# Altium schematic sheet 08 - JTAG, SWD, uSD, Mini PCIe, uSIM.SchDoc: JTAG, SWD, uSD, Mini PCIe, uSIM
size A3; PageSetup: Record=PageOptions¦CenterHorizontal=True¦CenterVertical=True¦PrintScale=0.70¦XCorrection=1.00¦YCorrection=1.00¦PrintKind=0¦BorderSize=5000000¦LeftOffset=0¦BottomOffset=0¦Orientation=2¦PaperLength=4200¦PaperWidth=2970¦Scale=100¦PaperSource=7¦PrintQuality=600¦MediaType=1¦DitherType=10¦PaperKind=A4¦PrintScaleMode=1; Author: Juan Anzola; SheetNumber: 8; SheetTotal: 20
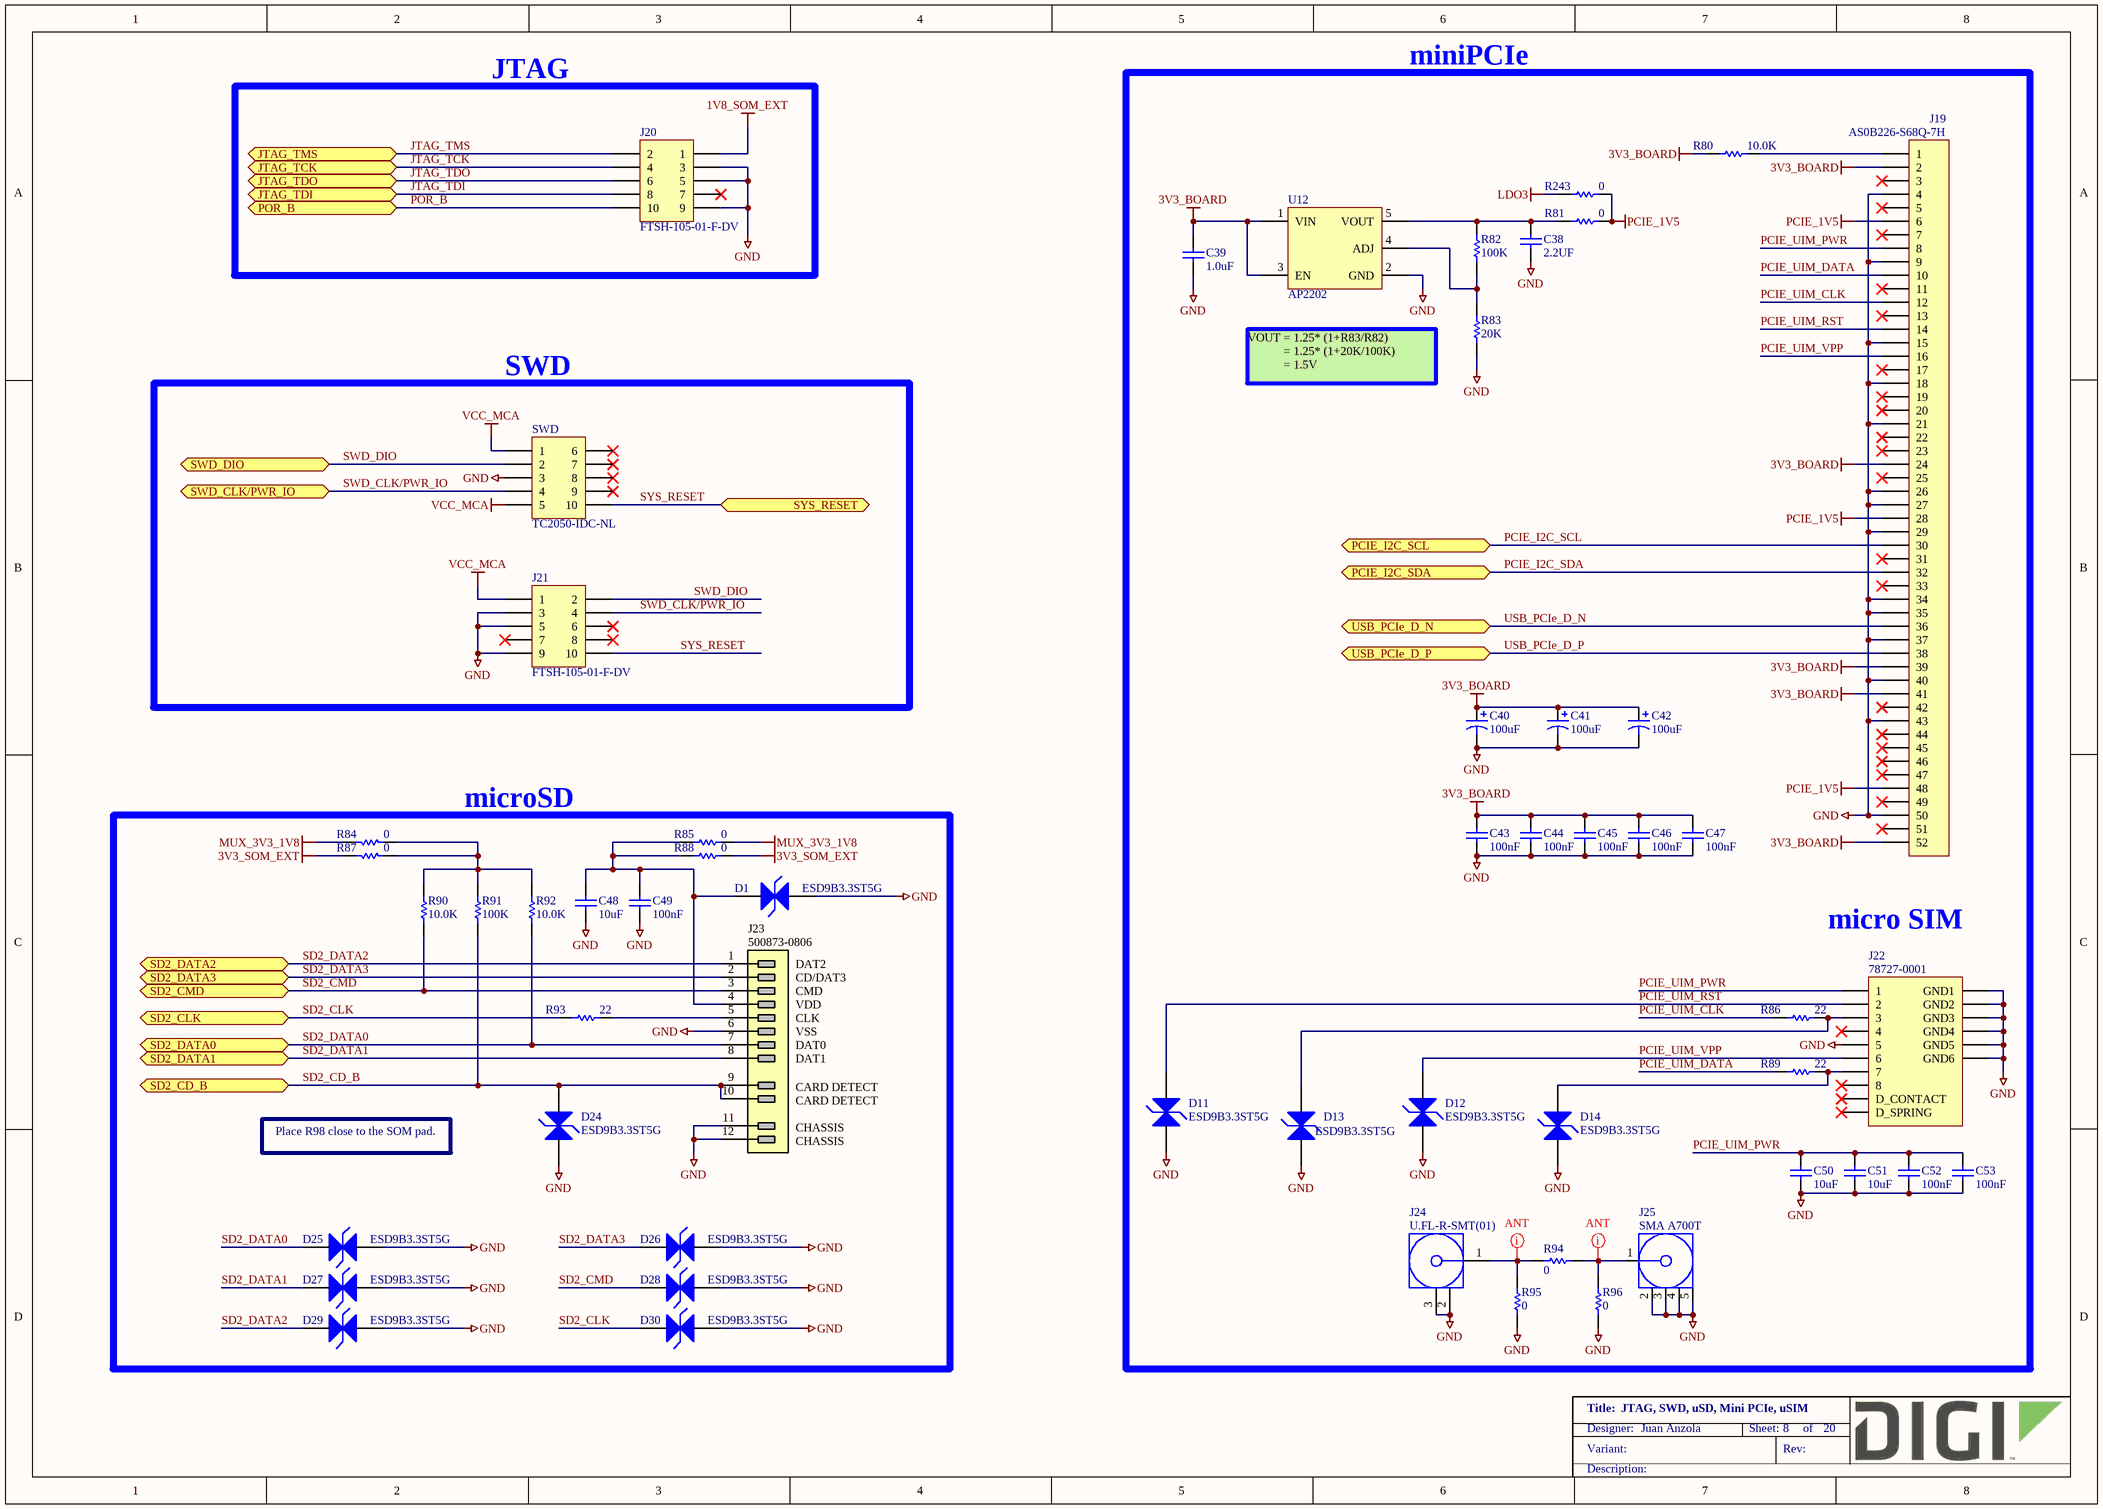
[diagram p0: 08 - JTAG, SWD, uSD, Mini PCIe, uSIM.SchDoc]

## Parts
C38  2.2UF  [CAPC1608X90N]
C39  1.0uF  [CAPC1005X55N]
C40  100uF  [CAPMP3216X120N]
C41  100uF  [CAPMP3216X120N]
C42  100uF  [CAPMP3216X120N]
C43  100nF  [CAPC1005X55N]
C44  100nF  [CAPC1005X55N]
C45  100nF  [CAPC1005X55N]
C46  100nF  [CAPC1005X55N]
C47  100nF  [CAPC1005X55N]
C48  10uF  [CAPC1005X55N]
C49  100nF  [CAPC1005X55N]
C50  10uF  [CAPC2013X135N]
C51  10uF  [CAPC2013X135N]
C52  100nF  [CAPC1005X55N]
C53  100nF  [CAPC1005X55N]
D1  ESD9B3.3ST5G  [SODFL1006X43AN12]
D11  ESD9B3.3ST5G  [SODFL1006X43AN12]
D12  ESD9B3.3ST5G  [SODFL1006X43AN12]
D13  ESD9B3.3ST5G  [SODFL1006X43AN12]
D14  ESD9B3.3ST5G  [SODFL1006X43AN12]
D24  ESD9B3.3ST5G  [SODFL1006X43AN12]
D25  ESD9B3.3ST5G  [SODFL1006X43AN12]
D26  ESD9B3.3ST5G  [SODFL1006X43AN12]
D27  ESD9B3.3ST5G  [SODFL1006X43AN12]
D28  ESD9B3.3ST5G  [SODFL1006X43AN12]
D29  ESD9B3.3ST5G  [SODFL1006X43AN12]
D30  ESD9B3.3ST5G  [SODFL1006X43AN12]
J19  Manufacturer_Part_Number: AS0B226-S68Q-7H  [FOXCONN_AS0B221-S68Q-7H]  (hidden comment: PCIe Minicard)
J20  FTSH-105-01-F-DV  [SAMTEC_FTSH-105-01-F-DV]
J21  FTSH-105-01-F-DV  [SAMTEC_FTSH-105-01-F-DV]
J22  78727-0001  [MOLEX_78727-0001]
J23  500873-0806  [MOLEX_500873-0806]
J24  U.FL-R-SMT(01)  [HIROSE_U.FL-R-SMT(01)]
J25  SMA A700T  [BOBBINTRON_SMA A700T]
R80  10.0K  [RESC1005X40N]
R81  0  [RESC1005X40N]
R82  100K  [RESC1005X40N]
R83  20K  [RESC1609X55N]
R84  0  [RESC1005X40N]
R85  0  [RESC1005X40N]
R86  22  [RESC1005X40N]
R87  0  [RESC1005X40N]
R88  0  [RESC1005X40N]
R89  22  [RESC1005X40N]
R90  10.0K  [RESC1005X40N]
R91  100K  [RESC1005X40N]
R92  10.0K  [RESC1005X40N]
R93  22  [RESC1005X40N]
R94  0  [RESC1005X40N]
R95  0  [RESC1005X40N]
R96  0  [RESC1005X40N]
R243  0  [RESC1005X40N]
SWD  TC2050-IDC-NL  [TC_TC2050-IDC-NL]  (no BOM)
U12  AP2202  [SOT95P280X145-5N]

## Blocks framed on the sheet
JTAG: J20
SWD: J21 SWD
microSD: C48 C49 D1 D24-D30 J23 R84 R85 R87 R88 R90-R93

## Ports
JTAG_TCK (bidir), JTAG_TDI (bidir), JTAG_TDO (bidir), JTAG_TMS (bidir), PCIE_I2C_SCL (bidir), PCIE_I2C_SDA (bidir), POR_B (bidir), SD2_CD_B (bidir), SD2_CLK (bidir), SD2_CMD (bidir), SD2_DATA0 (bidir), SD2_DATA1 (bidir), SD2_DATA2 (bidir), SD2_DATA3 (bidir), SWD_CLK/PWR_IO (bidir), SWD_DIO (bidir), SYS_RESET (bidir), USB_PCIe_D_N (bidir), USB_PCIe_D_P (bidir)

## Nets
1V8_SOM_EXT: J20.1
3V3_BOARD: C39.1 C40.1 C41.1 C42.1 C43.2 C44.2 C45.2 C46.2 C47.2 J19.2 J19.24 J19.39 J19.41 J19.52 R80.2 U12.1(VIN) U12.3(EN)
3V3_SOM_EXT: R87.2 R88.2
GND: C38.1 C39.2 C40.2 C41.2 C42.2 C43.1 C44.1 C45.1 C46.1 C47.1 C48.1 C49.1 C50.1 C51.1 C52.1 C53.1 D1.2 D11.1 D12.1 D13.1 D14.1 D24.2 D25.2 D26.2 D27.2 D28.2 D29.2 D30.2 J19.4 J19.9 J19.15 J19.18 J19.21 J19.26 J19.27 J19.29 J19.34 J19.35 J19.37 J19.40 J19.43 J19.50 J20.3 J20.5 J20.9 J21.3 J21.5 J21.9 J22.5 J22.11(GND1) J22.12(GND2) J22.13(GND3) J22.14(GND4) J22.15(GND5) J22.16(GND6) J23.6 J23.11 J23.12 J24.2(GND) J24.3(GND) J25.2(GND) J25.3(GND) J25.4(GND) J25.5(GND) R83.1 R95.1 R96.1 SWD.3 U12.2(GND)
LDO3: R243.1
MUX_3V3_1V8: R84.2 R85.2
PCIE_1V5: J19.6 J19.28 J19.48 R81.2 R243.2
VCC_MCA: J21.1 SWD.1 SWD.5
JTAG_TCK: J20.4 ; port JTAG_TCK
JTAG_TDI: J20.8 ; port JTAG_TDI
JTAG_TDO: J20.6 ; port JTAG_TDO
JTAG_TMS: J20.2 ; port JTAG_TMS
PCIE_I2C_SCL: J19.30 ; port PCIE_I2C_SCL
PCIE_I2C_SDA: J19.32 ; port PCIE_I2C_SDA
PCIE_UIM_CLK: J19.12 R86.1
PCIE_UIM_DATA: J19.10 R89.1
PCIE_UIM_PWR: C50.2 C51.2 C52.2 C53.2 J19.8 J22.1
PCIE_UIM_RST: D11.2 J19.14 J22.2
PCIE_UIM_VPP: D12.2 J19.16 J22.6
POR_B: J20.10 ; port POR_B
SD2_CD_B: D24.1 J23.9 J23.10 R91.2 ; port SD2_CD_B
SD2_CLK: D30.1 R93.1 ; port SD2_CLK
SD2_CMD: D28.1 J23.3 R90.1 ; port SD2_CMD
SD2_DATA0: D25.1 J23.7 R92.1 ; port SD2_DATA0
SD2_DATA1: D27.1 J23.8 ; port SD2_DATA1
SD2_DATA2: D29.1 J23.1 ; port SD2_DATA2
SD2_DATA3: D26.1 J23.2 ; port SD2_DATA3
SWD_CLK/PWR_IO: J21.4 SWD.4 ; port SWD_CLK/PWR_IO
SWD_DIO: J21.2 SWD.2 ; port SWD_DIO
SYS_RESET: J21.10 SWD.10 ; port SYS_RESET
USB_PCIe_D_N: J19.36 ; port USB_PCIe_D_N
USB_PCIe_D_P: J19.38 ; port USB_PCIe_D_P
NetC38_2: C38.2 R81.1 R82.2 U12.5(VOUT)
NetC48_2: C48.2 C49.2 D1.1 J23.4 R85.1 R88.1
NetD13_2: D13.2 J22.3 R86.2
NetD14_2: D14.2 J22.7 R89.2
NetJ19_1: J19.1 R80.1
NetJ23_5: J23.5 R93.2
NetJ24_1: J24.1(Signal) R94.1 R95.2
NetJ25_1: J25.1(Signal) R94.2 R96.2
NetR82_1: R82.1 R83.2 U12.4(ADJ)
NetR84_1: R84.1 R87.1 R90.2 R91.1 R92.2

Not connected (* = marked no-connect by the designer): J19 3* 5* 7* 11* 13* 17* 19* 20* 22* 23* 25* 31* 33* 42* 44* 45* 46* 47* 49* 51*; J20 7*; J21 6* 7* 8*; J22 4* 8* 9(D_CONTACT)* 10(D_SPRING)*; SWD 6* 7* 8* 9*

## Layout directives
net class ANT: NetJ24_1, NetJ25_1

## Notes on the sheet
- miniPCIe
- VOUT = 1.25* (1+R83/R82)
  = 1.25* (1+20K/100K)
  = 1.5V
- micro SIM
- Place R98 close to the SOM pad.

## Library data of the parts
C38 = 1001303: CAP CER 2.2UF 16V 10% X5R 0603; Part_Type: Capacitor; Manufacturer: TDK Corporation; Manufacturer_Part_Number: C1608X5R1C225K080AB; Digi_PN: 14050730; Component_Life_Cycle_State: Reviewed; Area: 2,27
C39 = 1001167: CAP CER 1UF 10V 10% X5R 0402; Part_Type: Capacitor; Manufacturer: Murata; Manufacturer_Part_Number: GRM155R61A105KE15D; Digi_PN: 14050399; Component_Life_Cycle_State: Reviewed; Area: 0,95
C40-C42 = 1001196: CAP TANT 100UF 6.3V 20% 1206; Part_Type: Capacitor; Manufacturer: Rohm; Manufacturer_Part_Number: TCTAL0J107M8R; Digi_PN: 14050490; Component_Life_Cycle_State: Reviewed; Area: 8.01; Project: CCWMX6_SBC board
C43-C47 C49 C52 C53 = 1000006: CAP 100nF 16V 10% X7R 0402; Part_Type: Capacitor; Manufacturer: Murata; Manufacturer_Part_Number: GRM155R71C104KA88D; Component_Life_Cycle_State: CAD Reviewed; Area: 0.95; Project: KITT; Tolerance: 10; Digi_PN: 14050552
C48 = 1001168: CAP CER 10UF 10V 20% X5R 0402; Part_Type: Capacitor; Manufacturer: Samsung; Manufacturer_Part_Number: CL05A106MP5NUNC; Digi_PN: 14050689; Component_Life_Cycle_State: Reviewed; Area: 0.95; Project: CCWMX6_SBC board
C50 C51 = 1000111: CAP CER 10UF 16V 10% X5R 0805; Part_Type: Capacitor; Manufacturer: Murata; Manufacturer_Part_Number: GRM21BR61C106KE15L; Digi_PN: 14050701; Component_Life_Cycle_State: Proven; Area: 3.99; Project: Adjustable Foundation; Tolerance: 10
D1 D11-D14 D24-D30 = 1001637: TVS DIODE 3.3VWM SOD923; Part_Type: Diodes; Manufacturer: On Semiconductor; Digi_PN: 17050883; Component_Life_Cycle_State: Reviewed; Area: 1,01
J19 = 1001130: SMCONN,MINI PCI EXP, 6.8MM HT; Part_Type: Connector; Manufacturer: Foxconn; Digi_PN: 18000349; Component_Life_Cycle_State: Reviewed; Area: 150; Project: CCWMX6_SBC board
J20 = 1000034: CONN HEADER 10POS DUAL .05" SMD; Part_Type: Connector; Manufacturer: Samtec; Note: 18000715 = Digi No. for GE WDNU; Digi_PN: 18000539; Component_Life_Cycle_State: Proven; Area: 43.55; Project: Adjustable Foundation
J21 = 1000034: CONN HEADER 10POS DUAL .05" SMD; Part_Type: Connector; Manufacturer: Samtec; Note: 18000715 = Digi No. for GE WDNU; Digi_PN: 18000539; Component_Life_Cycle_State: Proven; Area: 43,55; Project: Adjustable Foundation
J22 = 1001120: MEMORY CARD 6POS PUSH/PULL SMD; Part_Type: Connector; Manufacturer: Molex; Digi_PN: 18000638; Component_Life_Cycle_State: Reviewed; Area: 217; Project: CCWMX6_SBC board
J23 = 1001118: CONN TRANSFLSH R/A PUSH-PUSH SMD; Part_Type: Connector; Manufacturer: Molex; Digi_PN: MB03015; Component_Life_Cycle_State: Reviewed; Area: 213; Project: CCWMX6_SBC board
J24 = 1000027: RF Connectors U.FL RECEPTACLE SMT GLD M CONTACT; Manufacturer: Hirose; Digi_PN: 18000684; Component_Life_Cycle_State: Proven; Area: 14,4
J25 = 1002720: CONN SMA JACK R/A 50 OHM L15.1MM PCB TH; Part_Type: Connector; Manufacturer: Bobbintron Electrical Corp; Digi_PN: MA02979; Component_Life_Cycle_State: Reviewed; Area: 121,68
R80 R90 R92 = 1000537: RES 10.0K OHM 1/10W 1% 0402 SMD; Part_Type: Resistor; Manufacturer: Panasonic - ECG; Manufacturer_Part_Number: ERJ-2RKF1002X; Component_Life_Cycle_State: CAD Reviewed; Area: 0.95; Project: KITT; Power_WV_SRF: 100; Digi_PN: 13051084
R81 R94-R96 R243 = 1000076: RES 0.0 OHM 1/10W 0402 SMD; Part_Type: Resistor; Manufacturer: Panasonic - ECG; Manufacturer_Part_Number: ERJ-2GE0R00X; Digi_PN: 13050387; Component_Life_Cycle_State: Proven; Area: 0,95; Power_WV_SRF: 10
R82 = 1000480: RES 100K OHM 1/10W 1% 0402 SMD; Part_Type: Resistor; Manufacturer: Panasonic - ECG; Manufacturer_Part_Number: ERJ-2RKF1003X; Digi_PN: 13051063; Component_Life_Cycle_State: CAD Reviewed; Area: 0,95; Power_WV_SRF: 100
R83 = 1000142: RES 20K OHM 1/10W 5% 0603 SMD; Part_Type: Resistor; Manufacturer: Panasonic - ECG; Manufacturer_Part_Number: ERJ-3GEYJ203V; Digi_PN: 13050013; Component_Life_Cycle_State: Reviewed; Area: 2,5; Power_WV_SRF: 100; Tolerance: 5
R84 R85 R87 R88 = 1000076: RES 0.0 OHM 1/10W 0402 SMD; Part_Type: Resistor; Manufacturer: Panasonic - ECG; Manufacturer_Part_Number: ERJ-2GE0R00X; Component_Life_Cycle_State: Proven; Area: 0.95; Project: Adjustable Foundation; Power_WV_SRF: 10; Digi_PN: 13050387
R86 R89 R93 = 1000601: RES 22.0 OHM 1/10W 1% 0402 SMD; Part_Type: Resistor; Manufacturer: Panasonic - ECG; Manufacturer_Part_Number: ERJ-2RKF22R0X; Digi_PN: 13051089; Component_Life_Cycle_State: CAD Reviewed; Area: 0,95; Power_WV_SRF: 100
R91 = 1000480: RES 100K OHM 1/10W 1% 0402 SMD; Part_Type: Resistor; Manufacturer: Panasonic - ECG; Manufacturer_Part_Number: ERJ-2RKF1003X; Digi_PN: 13051063; Component_Life_Cycle_State: CAD Reviewed; Area: 0.95; Project: KITT; Power_WV_SRF: 100
SWD = CAD0066: CBL PLUG-OF-NAILS 10-PIN; Part_Type: Test Point; Component_Life_Cycle_State: Created; Area: 8; Project: CCWMX6_SBC board
U12 = 1001979: IC REG LDO ADJ 0.15A SOT25; Part_Type: Regulator; Manufacturer: Diodes, Inc.; Manufacturer_Part_Number: AP2202K-ADJTRG1; Digi_PN: 17050874; Component_Life_Cycle_State: Reviewed; Area: 14,92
